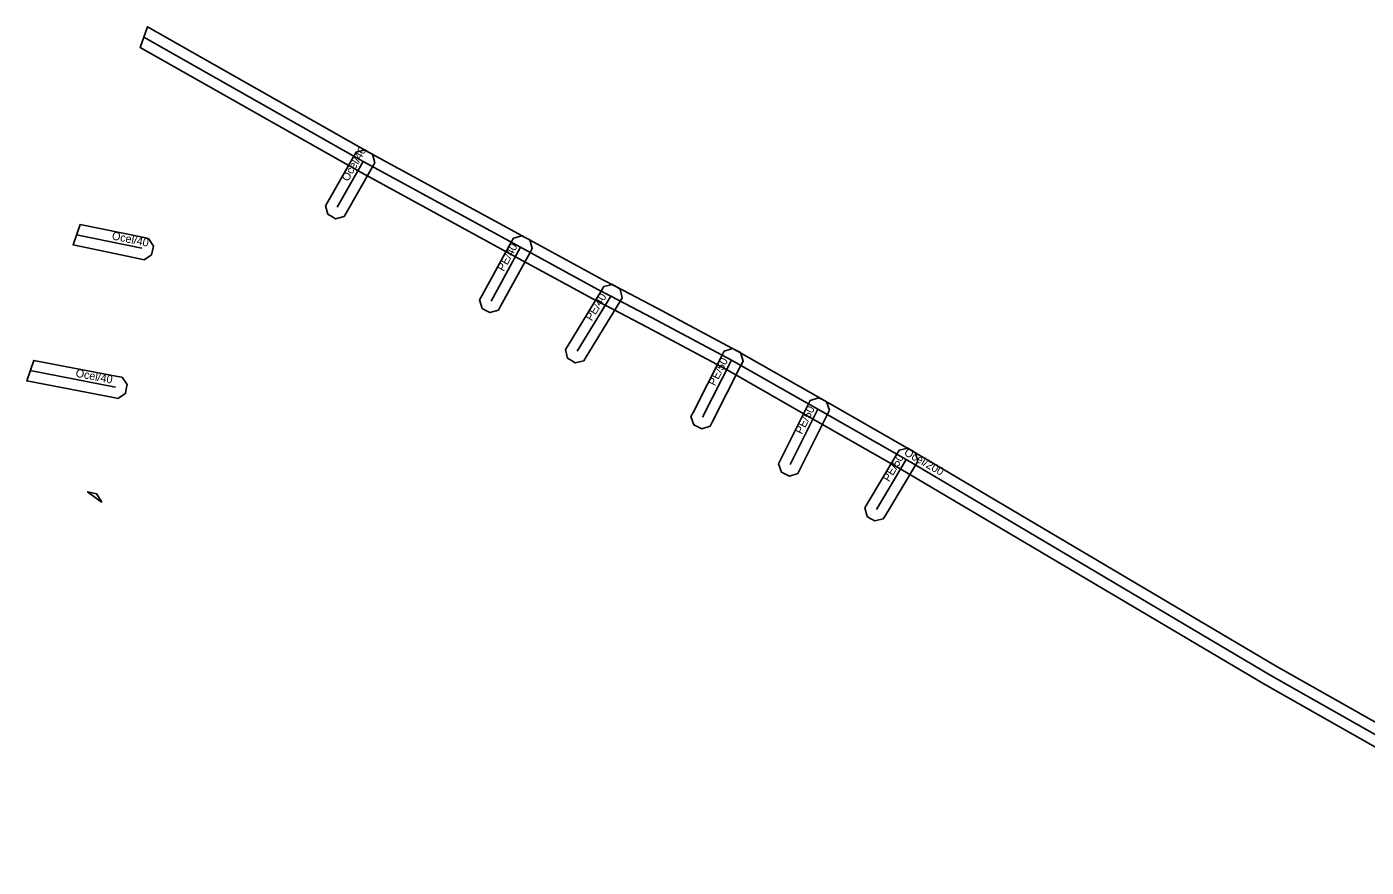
# Model space of a CAD drawing. Extents: x -702919 to -702657, y -1012371 to -1012107.
# Drawn here: x -702919 to -702794.8, y -1012227.2 to -1012149.3 of the extents above; entities that cross this region are included whole.
import ezdxf

# ---------------------------------------------------------------- set-up
doc = ezdxf.new("R2010")
doc.units = 0
for name, color, linetype in [('1', 7, 'Continuous'), ('14', 7, 'Continuous'), ('20', 7, 'Continuous')]:
    doc.layers.add(name, color=color, linetype=linetype)

msp = doc.modelspace()

# ---------------------------------------------------------------- linework, layer by layer
at = {"layer": '1'}
msp.add_lwpolyline([(-702790.46, -1012218.04), (-702804.11, -1012210.31), (-702837.92, -1012190.3), (-702846.13, -1012185.63), (-702854.1, -1012181.07), (-702861.46, -1012177.14), (-702865.3, -1012175.14), (-702866.49, -1012174.52), (-702873.67, -1012170.6), (-702888.27, -1012162.64), (-702908.47, -1012151.2), (-702907.81, -1012149.27), (-702887.3, -1012160.89), (-702872.71, -1012168.85), (-702865.55, -1012172.76), (-702864.37, -1012173.37), (-702860.53, -1012175.37), (-702853.13, -1012179.32), (-702845.13, -1012183.89), (-702836.92, -1012188.57), (-702803.11, -1012208.58), (-702789.55, -1012216.25)], dxfattribs=at)
for points in [[(-702891.29, -1012165.87), (-702891.08, -1012165.51), (-702888.65, -1012161.27), (-702888.45, -1012160.91), (-702887.65, -1012160.69), (-702887.29, -1012160.89), (-702886.93, -1012161.1), (-702886.71, -1012161.9), (-702886.92, -1012162.26), (-702889.35, -1012166.5), (-702889.56, -1012166.86), (-702890.35, -1012167.08), (-702890.71, -1012166.88), (-702891.07, -1012166.67)], [(-702908.52, -1012170.79), (-702914.7, -1012169.51), (-702914.05, -1012167.61), (-702908.11, -1012168.83), (-702907.71, -1012168.92), (-702907.25, -1012169.61), (-702907.34, -1012170.02), (-702907.42, -1012170.42), (-702908.11, -1012170.88)], [(-702877, -1012174.6), (-702876.8, -1012174.24), (-702874.06, -1012169.25), (-702873.86, -1012168.88), (-702873.07, -1012168.65), (-702872.71, -1012168.85), (-702872.34, -1012169.05), (-702872.11, -1012169.84), (-702872.31, -1012170.21), (-702875.05, -1012175.2), (-702875.25, -1012175.56), (-702876.04, -1012175.79), (-702876.41, -1012175.59), (-702876.77, -1012175.4)], [(-702863.77, -1012174.42), (-702863.98, -1012174.78), (-702867.11, -1012179.9), (-702867.32, -1012180.25), (-702868.13, -1012180.45), (-702868.48, -1012180.23), (-702868.83, -1012180.02), (-702869.03, -1012179.21), (-702868.81, -1012178.86), (-702865.69, -1012173.73), (-702865.47, -1012173.38), (-702864.67, -1012173.19), (-702864.31, -1012173.4), (-702863.96, -1012173.62)], [(-702857.39, -1012185.42), (-702857.2, -1012185.05), (-702854.51, -1012179.74), (-702854.32, -1012179.37), (-702853.53, -1012179.11), (-702853.16, -1012179.3), (-702852.79, -1012179.49), (-702852.54, -1012180.28), (-702852.72, -1012180.64), (-702855.42, -1012185.95), (-702855.61, -1012186.32), (-702856.39, -1012186.58), (-702856.76, -1012186.39), (-702857.13, -1012186.2)], [(-702910.95, -1012183.67), (-702919, -1012182.13), (-702918.35, -1012180.22), (-702910.57, -1012181.71), (-702910.16, -1012181.79), (-702909.7, -1012182.47), (-702909.78, -1012182.88), (-702909.85, -1012183.29), (-702910.54, -1012183.75)], [(-702844.55, -1012184.83), (-702844.73, -1012185.21), (-702847.29, -1012190.34), (-702847.47, -1012190.71), (-702848.25, -1012190.97), (-702848.62, -1012190.79), (-702849, -1012190.6), (-702849.26, -1012189.82), (-702849.08, -1012189.45), (-702846.53, -1012184.32), (-702846.34, -1012183.94), (-702845.56, -1012183.68), (-702845.19, -1012183.86), (-702844.81, -1012184.05)], [(-702836.35, -1012189.59), (-702836.56, -1012189.94), (-702839.33, -1012194.56), (-702839.55, -1012194.92), (-702840.35, -1012195.12), (-702840.7, -1012194.91), (-702841.06, -1012194.7), (-702841.26, -1012193.89), (-702841.05, -1012193.54), (-702838.28, -1012188.92), (-702838.07, -1012188.56), (-702837.26, -1012188.36), (-702836.91, -1012188.57), (-702836.55, -1012188.79)], [(-702912.06, -1012193.3), (-702912.08, -1012193.36), (-702913.35, -1012192.43), (-702912.92, -1012192.52), (-702912.52, -1012192.6)]]:
    msp.add_lwpolyline(points, close=True, dxfattribs=at)
at = {"layer": '14'}
for points in [[(-702908.14, -1012150.23), (-702887.78, -1012161.76), (-702873.19, -1012169.73), (-702866.02, -1012173.64), (-702864.83, -1012174.26), (-702860.99, -1012176.26), (-702853.62, -1012180.19), (-702845.63, -1012184.76), (-702837.42, -1012189.43), (-702803.61, -1012209.45), (-702790.01, -1012217.15), (-702768.25, -1012227.03), (-702767.42, -1012227.24)], [(-702890.22, -1012166.01), (-702887.78, -1012161.76)], [(-702914.38, -1012168.56), (-702908.32, -1012169.81)], [(-702875.92, -1012174.72), (-702873.19, -1012169.73)], [(-702864.83, -1012174.26), (-702867.96, -1012179.38)], [(-702918.67, -1012181.17), (-702910.76, -1012182.69)], [(-702856.31, -1012185.5), (-702853.62, -1012180.19)], [(-702845.63, -1012184.76), (-702848.18, -1012189.89)], [(-702837.42, -1012189.43), (-702840.19, -1012194.05)]]:
    msp.add_lwpolyline(points, dxfattribs=at)

# ---------------------------------------------------------------- texts
at = {"layer": '20'}
for s, rotation, p in [('Ocel/40', 60.181, (-702889.2, -1012163.68)), ('Ocel/40', 348.327, (-702911.15, -1012168.99)), ('PE/40', 61.2602, (-702874.76, -1012172.02)), ('PE/40', 58.6121, (-702866.6, -1012176.62)), ('PE/50', 63.0949, (-702855.16, -1012182.65)), ('Ocel/40', 349.1528, (-702914.51, -1012181.73)), ('PE/50', 63.5691, (-702847.1, -1012187.13)), ('Ocel/200', 330.368, (-702837.69, -1012188.96)), ('PE/50', 59.0545, (-702839.01, -1012191.54))]:
    msp.add_text(s, height=0.75, rotation=rotation, dxfattribs=at).set_placement(p)

doc.saveas('drawing.dxf')
